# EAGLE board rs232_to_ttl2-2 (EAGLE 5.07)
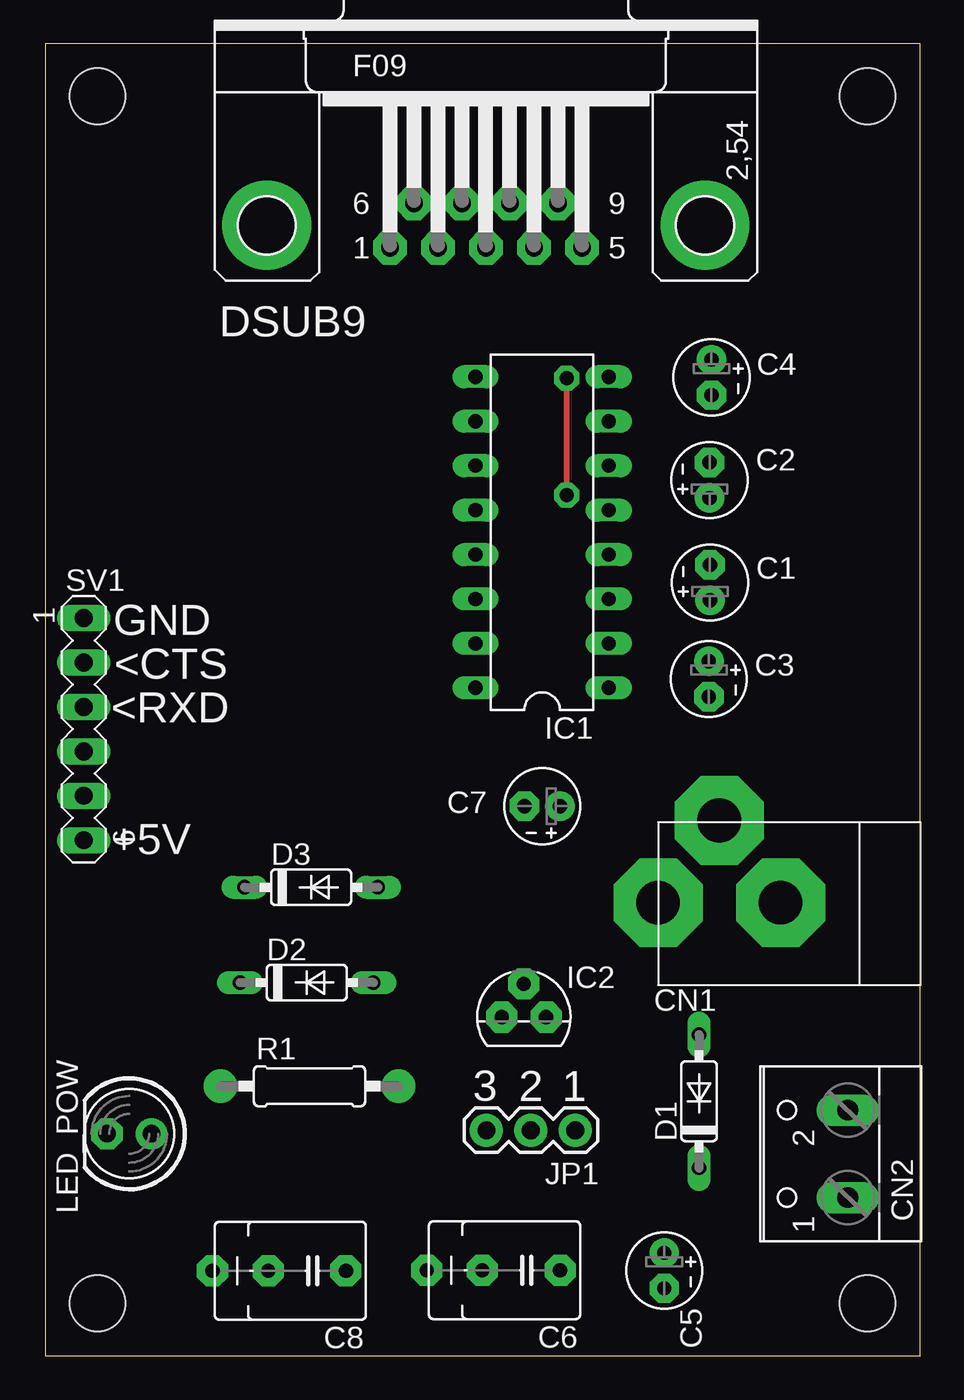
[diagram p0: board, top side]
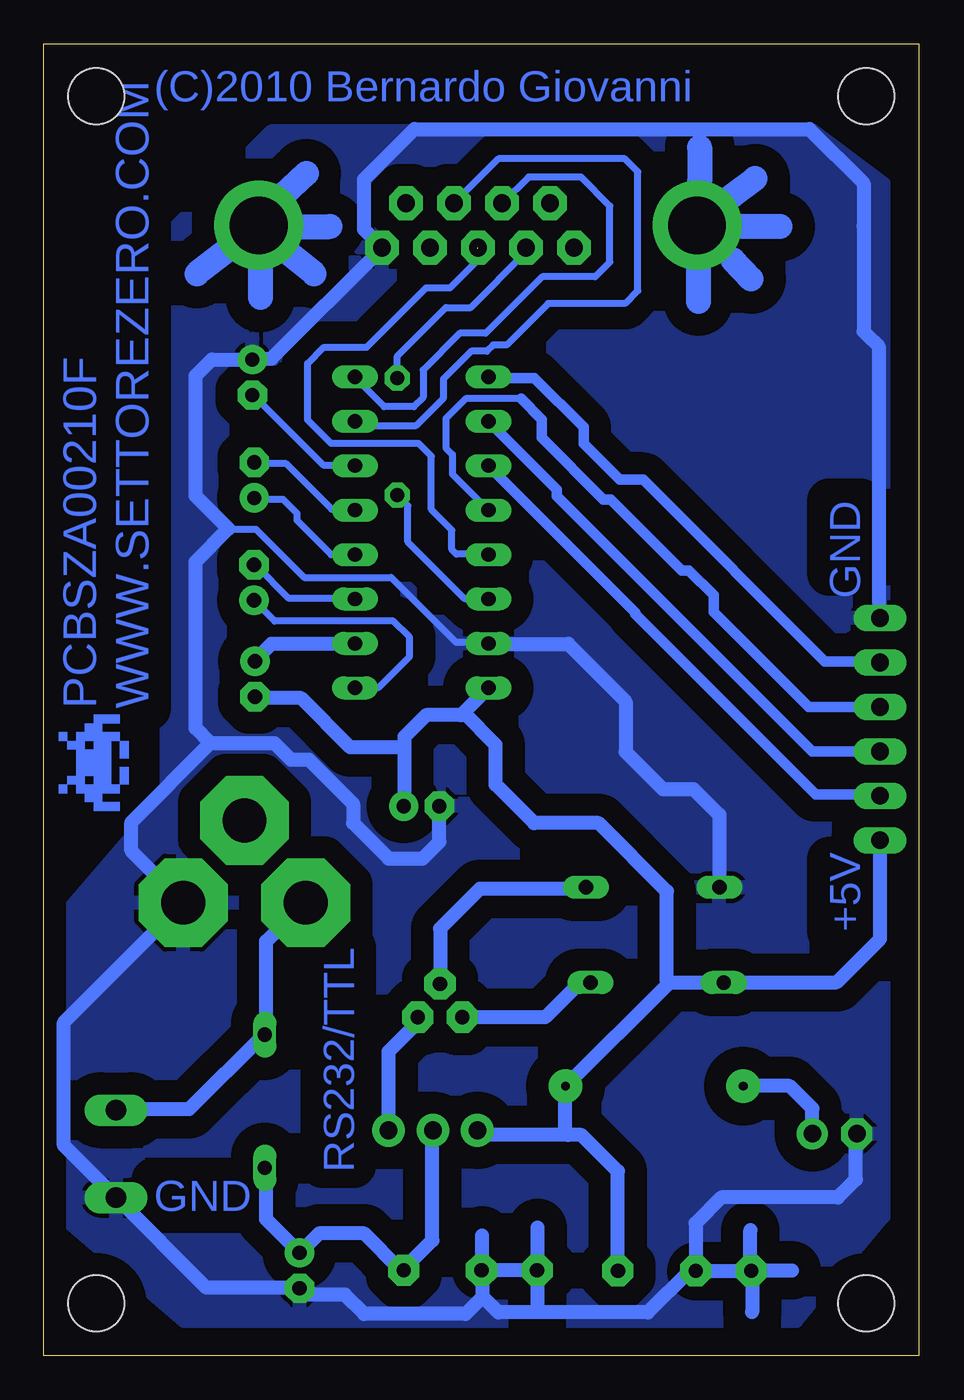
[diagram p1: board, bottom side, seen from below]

Size 50 x 75 mm. Coordinates in mm from the lower left corner, seen from the top.
Outline: 0,0 50,0 50,75 0,75 0,0
Copper layers (1*16): Top 0.035mm / dielectric 1.5mm / Bottom 0.035mm
Design rules "default *": minimum track width 12mil, minimum drill 24mil, track to track 11mil, track to pad 11mil, pad to pad 11mil, via to via 11mil, smd to smd 8mil, copper to edge 30mil, drill to drill 12mil, minimum pad ring 10mil, minimum via ring 8mil, stop-mask expansion 4mil, vias tented up to drill 0mil, thermal gap 10mil
Holes 3.2 mm at 3,72 47,72 47,3 3,3

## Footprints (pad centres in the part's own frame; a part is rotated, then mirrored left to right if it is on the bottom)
E2-4 = drill 0.813 pad 1.676 round: + -1.016,0 | drill 0.813 pad 1.676 octagon: - 1.016,0
C025_050-055X075 = drill 0.813 pad 1.778 octagon: 1 -1.27,0; 2 3.175,0; 3 6.35,0
POWER_SOCKET = drill 2.5 pad 5.08 octagon: CGND 4.6,-8; CSWI -0.098,-11.5; CVCC 4.6,-15
W237-102 = drill 1.194 long: 1 -2.5,-1.27; 2 2.5,-1.27
DO35-7 = drill 0.813 long: A 3.81,0; C -3.81,0
F09HP = drill 1.016 pad 1.93 octagon: 1 -5.486,-1.27; 2 -2.743,-1.27; 3 0,-1.27; 4 2.743,-1.27; 5 5.486,-1.27; 6 -4.115,1.27; 7 -1.372,1.27; 8 1.372,1.27; 9 4.115,1.27 | drill 3.302 pad 5.08 round: G1 -12.522,0; G2 12.522,0
DIL16 = drill 0.813 long: 1 -8.89,-3.81; 2 -6.35,-3.81; 3 -3.81,-3.81; 4 -1.27,-3.81; 5 1.27,-3.81; 6 3.81,-3.81; 7 6.35,-3.81; 8 8.89,-3.81; 9 8.89,3.81; 10 6.35,3.81; 11 3.81,3.81; 12 1.27,3.81; 13 -1.27,3.81; 14 -3.81,3.81; 15 -6.35,3.81; 16 -8.89,3.81
TO92 = drill 0.813 pad 1.778 octagon: 1 -1.27,0; 2 0,1.905; 3 1.27,0
1X03 = drill 1.016 pad 1.88 round: 1 0,0; 2 2.54,0; 3 5.08,0
LED5MM = drill 1 pad 1.778 round: A -1.27,0 | drill 1 pad 1.778 octagon: K 1.27,0
0207/10 = drill 0.5 pad 1.93 round: 1 -5.08,0; 2 5.08,0
MA06-1 = drill 1.016 long: 1 -6.35,0; 2 -3.81,0; 3 -1.27,0; 4 1.27,0; 5 3.81,0; 6 6.35,0

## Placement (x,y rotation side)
C1  1uF  [E2-4]  37.99,44.2 90 top
C2  1uF  [E2-4]  37.97,50.05 90 top
C3  1uF  [E2-4]  37.93,38.69 270 top
C4  1uF  [E2-4]  38.08,55.93 270 top
C5  1uF  [E2-4]  35.38,4.87 270 top
C6  100nF  [C025_050-055X075]  28.16,4.89 180 top
C7  1uF  [E2-4]  28.41,31.42 180 top
C8  10nF  [C025_050-055X075]  15.92,4.86 180 top
CN1  POWER_SOCKET  [POWER_SOCKET]  50.03,30.5 270 top
CN2  [W237-102]  44.6,11.54 90 top
D1  1N4148  [DO35-7]  37.37,14.55 90 top
D2  1N4148  [DO35-7]  14.95,21.33 0 top
D3  1N4148  [DO35-7]  15.2,26.78 0 top
DSUB9  DSUB9 FEMMINA  [F09HP]  25.19,64.62 0 top
IC1  MAX232  [DIL16]  28.4,47.07 90 top
IC2  78L05  [TO92]  27.36,19.36 0 top
JP1  [1X03]  30.3,12.89 180 top
LED_POW  [LED5MM]  4.81,12.69 180 top
R1  330R  [0207/10]  15.11,15.41 0 top
SV1  HEADER 6pin  [MA06-1]  2.21,35.82 270 top
U$1  [INVADER_5_5X4]  49.15,35.65 270 top

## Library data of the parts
C1-C8 = __mod_rcl
CN1 U$1 = __settorezero
CN2 = con-wago-500
D1-D3 = diode
DSUB9 = __mod_con-subd
IC1 = maxim
IC2 = __mod_linear
JP1 = SparkFun
LED_POW = __mod_led
R1 = rcl
SV1 = con-lstb

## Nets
0V: C4.+ C5.- C6.2 C7.- C8.2 CN1.CGND CN2.1 D3.C DSUB9.5 IC1.15 LED_POW.K SV1.1
+5V: C3.- C7.+ C8.1 D2.C IC1.16 JP1.3 R1.2 SV1.6
CSWI: CN1.CSWI
N$1: C1.+ IC1.1
N$2: CN1.CVCC CN2.2 D1.A
N$3: LED_POW.A R1.1
N$4: C1.- IC1.3
N$5: C2.+ IC1.4
N$6: C2.- IC1.5
N$7: C3.+ IC1.2
N$8: DSUB9.3 IC1.13
N$9: C4.- IC1.6
N$10: DSUB9.7 IC1.8
N$11: DSUB9.2 IC1.14
N$12: DSUB9.8 IC1.7
N$13: IC1.11 SV1.5
N$14: IC1.10 SV1.4
N$15: IC1.12 SV1.3
N$16: IC1.9 SV1.2
N$17: C5.+ C6.1 D1.C JP1.2
N$18: D3.A IC2.2
N$19: IC2.3 JP1.1
N$21: D2.A IC2.1

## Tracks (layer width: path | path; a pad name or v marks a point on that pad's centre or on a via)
0V
  Bottom 0.305: 12.7,4.9 C8.2 12.8,4.8 | 3.6,12.7 LED_POW.K | 35.4,3.9 C5.- 35.3,3.8 35,3.5 | 45.8,9 CN2.1 46,9.1 | 25,4.8 C6.2 24.9,4.7 | D3.C 11.4,26.8 | 24.5,40.7 IC1.15 24.7,40.8 | 2.3,42.2 SV1.1 | 38,57 C4.+ 38.1,56.8 | 30.7,63.3 DSUB9.5 30.8,63.4 | 27.4,31.4 C7.- | 42,25.9 CN1.CGND 42.1,25.8
  Bottom 0.406: 24.7,40.8 26.45,40.8 30.15,44.5 35.12,44.5 37.88,47.25 39.38,47.25 39.4,47.27 39.45,47.27 | 12.8,4.8 13.15,4.8 | 24.93,4.83 C6.2 | C8.2 | C4.+
  Bottom 0.61: 3.15,58.55 3,58.4
  Bottom 0.813: 35.4,3.9 40.7,3.9 45.8,9 | 2.3,42.2 2.3,57.7 3,58.4 | 38,57 37,57 30.7,63.3 | DSUB9.5 31.7,64.37 31.7,67.25 28.82,70.12 6.25,70.12 3.15,67.03 3.15,64.6 3.15,58.55 | 27.4,31.4 27.4,29.38 28.35,28.42 30.3,28.42 32.33,30.45 32.33,31.55 34.85,34.08 35.88,34.08 36.83,35.02 40.48,35.02 | 40.48,35.02 41.33,35.88 41.33,45.4 39.45,47.27 41.33,49.15 41.33,56.02 40.4,56.95 C4.+ | 40.48,35.02 45,30.5 45,28.87 CN1.CGND | 42.1,25.8 48.85,19.05 48.85,12.02 CN2.1 | 13.15,4.8 15.47,2.47 24.02,2.47 24.93,3.38 | 24.93,3.38 24.93,4.83 | 35,3.5 32.8,3.5 31.7,2.4 25.9,2.4 24.93,3.38 | 3.6,12.7 3.6,10.07 4.62,9.05 11.28,9.05 12.75,7.57 C8.2 | 24.5,40.7 20.02,40.7 20.02,40.67 16.75,37.4 16.75,34.52 14.62,32.4 12.88,32.4 11.4,30.92 D3.C
  pour Bottom (isolate 1.27): 6.15,70.08 37,70 43,64 43,32 49,25 49,8 42,2 7,2 2,8 2,67 6,70
+5V
  Bottom 0.305: 29.4,31.5 C7.+ 29.5,31.6 | 37.9,37.6 C3.- | C8.1 17.2,4.9 | JP1.3 25.2,12.9 | 20.2,15.3 R1.2 | 14.3,21.3 14.4,21.4
  Bottom 0.406: 26.01,36.76 26.14,36.62 | 29.4,34.83 29.45,34.77
  Bottom 0.813: R1.2 14.3,21.3 14.25,21.35 11.16,21.35 | 29.4,31.5 29.4,34.83 29.4,35.38 28.15,36.62 26.14,36.62 | IC1.16 26.01,36.76 24.18,34.92 24.18,32.65 21.98,30.45 18.3,30.45 14.4,26.55 14.4,21.4 | 37.9,37.6 35.3,37.6 32.48,34.77 29.45,34.77 | 17.2,4.9 17.2,10.55 19.27,12.62 20.05,12.62 | 20.05,12.62 24.95,12.62 JP1.3 | 20.2,15.3 20.2,12.77 20.05,12.62 | SV1.6 2.21,23.84 4.7,21.35 11.16,21.35 | 11.16,21.35 D2.C
N$1
  Bottom 0.305: C1.+ 37.9,43.1
  Bottom 0.406: IC1.1 30.89,38.18 29.1,39.98 29.1,41.08 30.02,42 36.81,42 C1.+
N$2
  Bottom 0.305: 37.3,18.4 D1.A 37.5,18.3 | 35.1,25.9 CN1.CVCC | 45.8,14.1 CN2.2
  Bottom 0.813: 37.3,18.4 37.3,23.7 35.1,25.9 | 45.8,14.1 41.7,14.1 37.5,18.3
N$3
  Bottom 0.305: R1.1 10,15.4
  Bottom 0.813: LED_POW.A 6.08,14.13 7.38,15.43 10.02,15.43 R1.1
N$4
  Bottom 0.305: IC1.3 32.3,43.3 | 37.9,45.2 C1.-
  Bottom 0.406: 32.3,43.3 36,43.3 37.9,45.2
N$5
  Bottom 0.305: C2.+ 37.9,49
  Bottom 0.406: IC1.4 33.58,45.8 35.52,47.75 35.52,48.15 36.33,48.95 37.89,48.95 C2.+
N$6
  Bottom 0.305: IC1.5 32.3,48.4 | C2.- 37.9,51
  Bottom 0.406: 32.3,48.4 33.55,48.4 36.15,51 37.9,51 C2.-
N$7
  Bottom 0.305: 32.3,40.7 IC1.2 | 37.9,39.8 C3.+
  Bottom 0.813: 32.3,40.7 37,40.7 37.9,39.8
N$8  (1 unrouted)
  Bottom 0.305: IC1.13 24.9,45.8
  Bottom 0.406: 25.2,63.3 25.2,62.62 26.77,61.05 28.15,61.05 31.55,57.65 34,57.65 34.92,56.73 34.92,53.5 33.58,52.15 28.57,52.15 27.85,51.42 27.85,48.38 26.68,47.2 26.68,46.08 26.43,45.83 24.61,45.83 IC1.13
N$9
  Bottom 0.305: IC1.6 32.3,50.9 | 38,54.9 C4.-
  Bottom 0.406: 32.3,50.9 34,50.9 38,54.9
N$10
  Bottom 0.305: 23.8,65.9 DSUB9.7 | 32.21,55.91 IC1.8
  Bottom 0.406: 32.21,55.91 30.55,54.25 28.85,54.25 28.32,54.77 28.32,56.35 26.23,58.45 24.75,58.45 21.52,61.67 18.5,61.67 17.65,62.53 17.65,65.72 19.3,67.38 22.3,67.38 23.77,65.9 23.8,65.9
N$11  (via drill 0.8 pad 1.42)
  Top 0.305: v29.8,49.2 v29.8,55.88
  Bottom 0.406: v29.8,49.2 29.2,48.6 29.2,46.52 25.93,43.26 IC1.14 | DSUB9.2 22.45,63.08 25.6,59.92 27.02,59.92 29.8,57.15 v29.8,55.88
N$12
  Bottom 0.305: DSUB9.8 26.5,65.9
  Bottom 0.406: DSUB9.8 24.03,68.42 16.8,68.42 16.05,67.67 16.05,60.88 16.77,60.15 21.18,60.15 23.55,57.77 24.32,57.77 24.68,57.42 25.57,57.42 27.15,55.85 27.15,54.75 28.73,53.17 32.02,53.17 32.21,53.36 IC1.7
N$13
  Bottom 0.305: 24.5,50.6 24.5,50.8 IC1.11 | SV1.5 2.3,32.1
  Bottom 0.61: 2.3,32.1 5.9,32.1 16.2,42.4 16.2,42.49 IC1.11
N$14
  Bottom 0.305: IC1.10 24.5,53.4
  Bottom 0.61: SV1.4 6.08,34.55 20.68,49.15 20.68,49.51 IC1.10
N$15
  Bottom 0.305: IC1.12 24.6,48.4 | SV1.3 2.3,37.1
  Bottom 0.406: IC1.12 26.65,50.4 26.65,51.52 27.02,51.9 27.02,53.58 25.9,54.7 22.73,54.7 | 11.6,42.4 11.72,42.4 11.72,42.51
  Bottom 0.61: 2.3,37.1 6.3,37.1 11.6,42.4 | 22.73,54.7 21.55,53.52 21.55,52.48 18.02,48.95 17.6,48.95 13.55,44.9 13.15,44.9 11.72,43.48 11.72,42.51
N$16
  Bottom 0.305: 24.5,55.9 IC1.9 | SV1.2 2.3,39.7
  Bottom 0.406: SV1.2 2.28,39.7
  Bottom 0.61: 24.5,55.9 21.98,55.9 19.15,53.08 19.15,52.15 17.07,50.08 15.75,50.08 5.38,39.7 2.28,39.7
N$17
  Bottom 0.305: 37.3,10.7 D1.C | 35.4,5.9 C5.+ 35.3,5.8 | 29.5,4.9 C6.1 29.4,5 | 27.8,12.8 JP1.2
  Bottom 0.406: 29.5,4.9 29.6,4.9
  Bottom 0.813: 27.8,12.8 27.8,6.6 29.4,5 | 29.6,4.9 31.7,7 34.27,7 C5.+ 37.3,7.81 37.3,10.7
N$18
  Bottom 0.305: D3.A 19.1,26.7 | IC2.2 27.3,21.3
  Bottom 0.406: IC2.2
  Bottom 0.813: 19.1,26.7 25.07,26.7 27.35,24.43 IC2.2
N$19
  Bottom 0.305: 28.7,19.3 IC2.3 | JP1.1
  Bottom 0.813: 28.7,19.3 28.7,19 30.3,17.4 JP1.1
N$20
  Bottom 1.422: 12.53,69.08 12.53,67.12
N$21
  Bottom 0.305: D2.A 18.8,21.3 | IC2.1 26,19.4
  Bottom 0.406: IC2.1
  Bottom 0.813: 18.8,21.3 19.4,21.3 21.35,19.35 IC2.1
N$22
  Bottom 1.422: 7.92,64.55 10.05,64.55
N$24
  Bottom 0.813: 9.57,4.82 12.72,4.82
N$25
  Bottom 0.813: 21.77,4.9 25,4.9
N$26
  Bottom 1.422: 12.6,62.3 12.6,60.28
N$27
  Bottom 1.422: 9.35,67.3 10.7,66.28
N$28
  Bottom 1.422: 9.57,61.55 10.62,62.65
N$29
  Bottom 1.422: 37.62,62.28 37.62,60.5
N$30
  Bottom 1.422: 39.52,63.2 41.25,61.85
N$31
  Bottom 1.422: 35.45,64.55 33.65,64.55
N$32
  Bottom 1.422: 36,63.03 34.55,61.85
N$33
  Bottom 1.422: 36.3,66.38 35,67.58
N$34
  Bottom 0.813: 9.62,5.65 9.62,7.18
N$35
  Bottom 0.813: 9.53,4.1 9.53,2.5
N$36
  Bottom 0.813: 8.88,4.88 7.25,4.88
N$37
  Bottom 0.813: 21.77,5.62 21.77,7.32
N$38
  Bottom 0.813: 21.8,4.12 21.8,2.6
N$39
  Bottom 0.813: 24.95,5.62 24.95,6.88

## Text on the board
Bottom: (C)2010 Bernardo Giovanni | GND | WWW.SETTOREZERO.COM | PCBSZA00210F | +5V | RS232/TTL | GND
tNames: GND | <CTS | <RXD | +5V | 3 | 2 | 1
